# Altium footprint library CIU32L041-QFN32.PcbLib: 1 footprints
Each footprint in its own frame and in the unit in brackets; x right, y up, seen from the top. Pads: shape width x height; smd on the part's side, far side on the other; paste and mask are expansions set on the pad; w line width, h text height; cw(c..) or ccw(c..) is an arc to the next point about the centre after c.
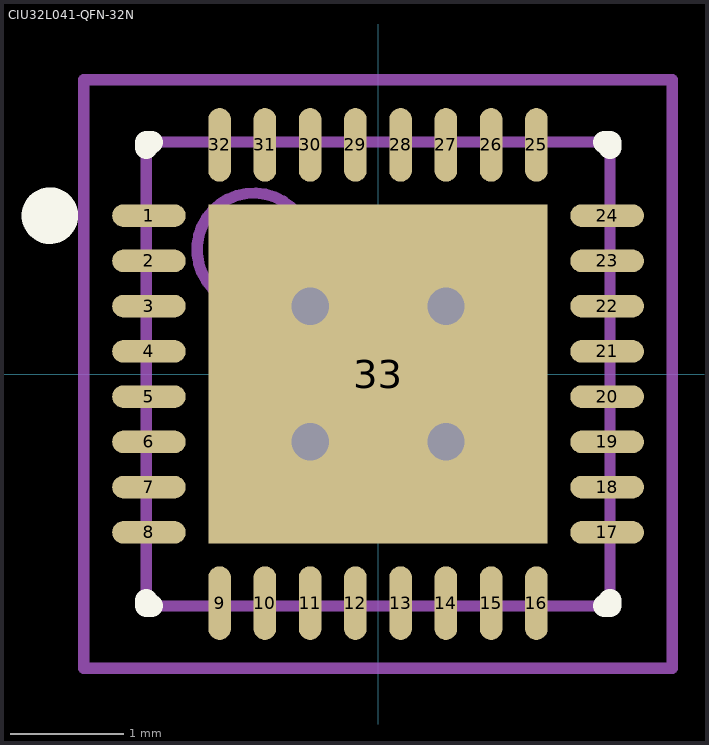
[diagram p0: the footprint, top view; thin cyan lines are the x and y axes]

## CIU32L041-QFN-32N [mm] "QFN, 32-Leads, Body 4.1x4.1mm (max), Pitch 0.40mm, IPC Medium Density"
height 0.8
pads (33):
  oval 0.65x0.2 smd: 1(-2.025,1.4) 2(-2.025,1) 3(-2.025,0.6) 4(-2.025,0.2) 5(-2.025,-0.2) 6(-2.025,-0.6) 7(-2.025,-1) 8(-2.025,-1.4) 17(2.025,-1.4) 18(2.025,-1) 19(2.025,-0.6) 20(2.025,-0.2) 21(2.025,0.2) 22(2.025,0.6) 23(2.025,1) 24(2.025,1.4)
  oval 0.2x0.65 smd: 9(-1.4,-2.025) 10(-1,-2.025) 11(-0.6,-2.025) 12(-0.2,-2.025) 13(0.2,-2.025) 14(0.6,-2.025) 15(1,-2.025) 16(1.4,-2.025) 25(1.4,2.025) 26(1,2.025) 27(0.6,2.025) 28(0.2,2.025) 29(-0.2,2.025) 30(-0.6,2.025) 31(-1,2.025) 32(-1.4,2.025)
  rect 3x3 smd: 33(0,0)
via -0.6,0.6 diameter 0.66 hole 0.33
via 0.6,0.6 diameter 0.66 hole 0.33
via -0.6,-0.6 diameter 0.66 hole 0.33
via 0.6,-0.6 diameter 0.66 hole 0.33
Top Overlay:
  circle w0.25: c-2.9,1.4 r0.125
  lines w0.2: -2.05,-2 -2.05,-2.05 -2,-2.05 ; -2.05,2 -2.05,2.05 -2,2.05 ; 2,-2.05 2.05,-2.05 2.05,-2 ; 2,2.05 2.05,2.05 2.05,2
Mechanical 13:
  circle w0.1: c-1.1,1.1 r0.5
  lines w0.1: -2.05,-2.05 -2.05,2.05 2.05,2.05 2.05,-2.05 -2.05,-2.05
Mechanical 15:
  lines w0.1: -0.5,0 0.5,0 ; 0,-0.5 0,0.5 ; -2.6,-2.6 -2.6,2.6 2.6,2.6 2.6,-2.6 -2.6,-2.6
3D body: height 0.8, standoff 0.02, extent -2.05,-2.05 2.05,2.05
